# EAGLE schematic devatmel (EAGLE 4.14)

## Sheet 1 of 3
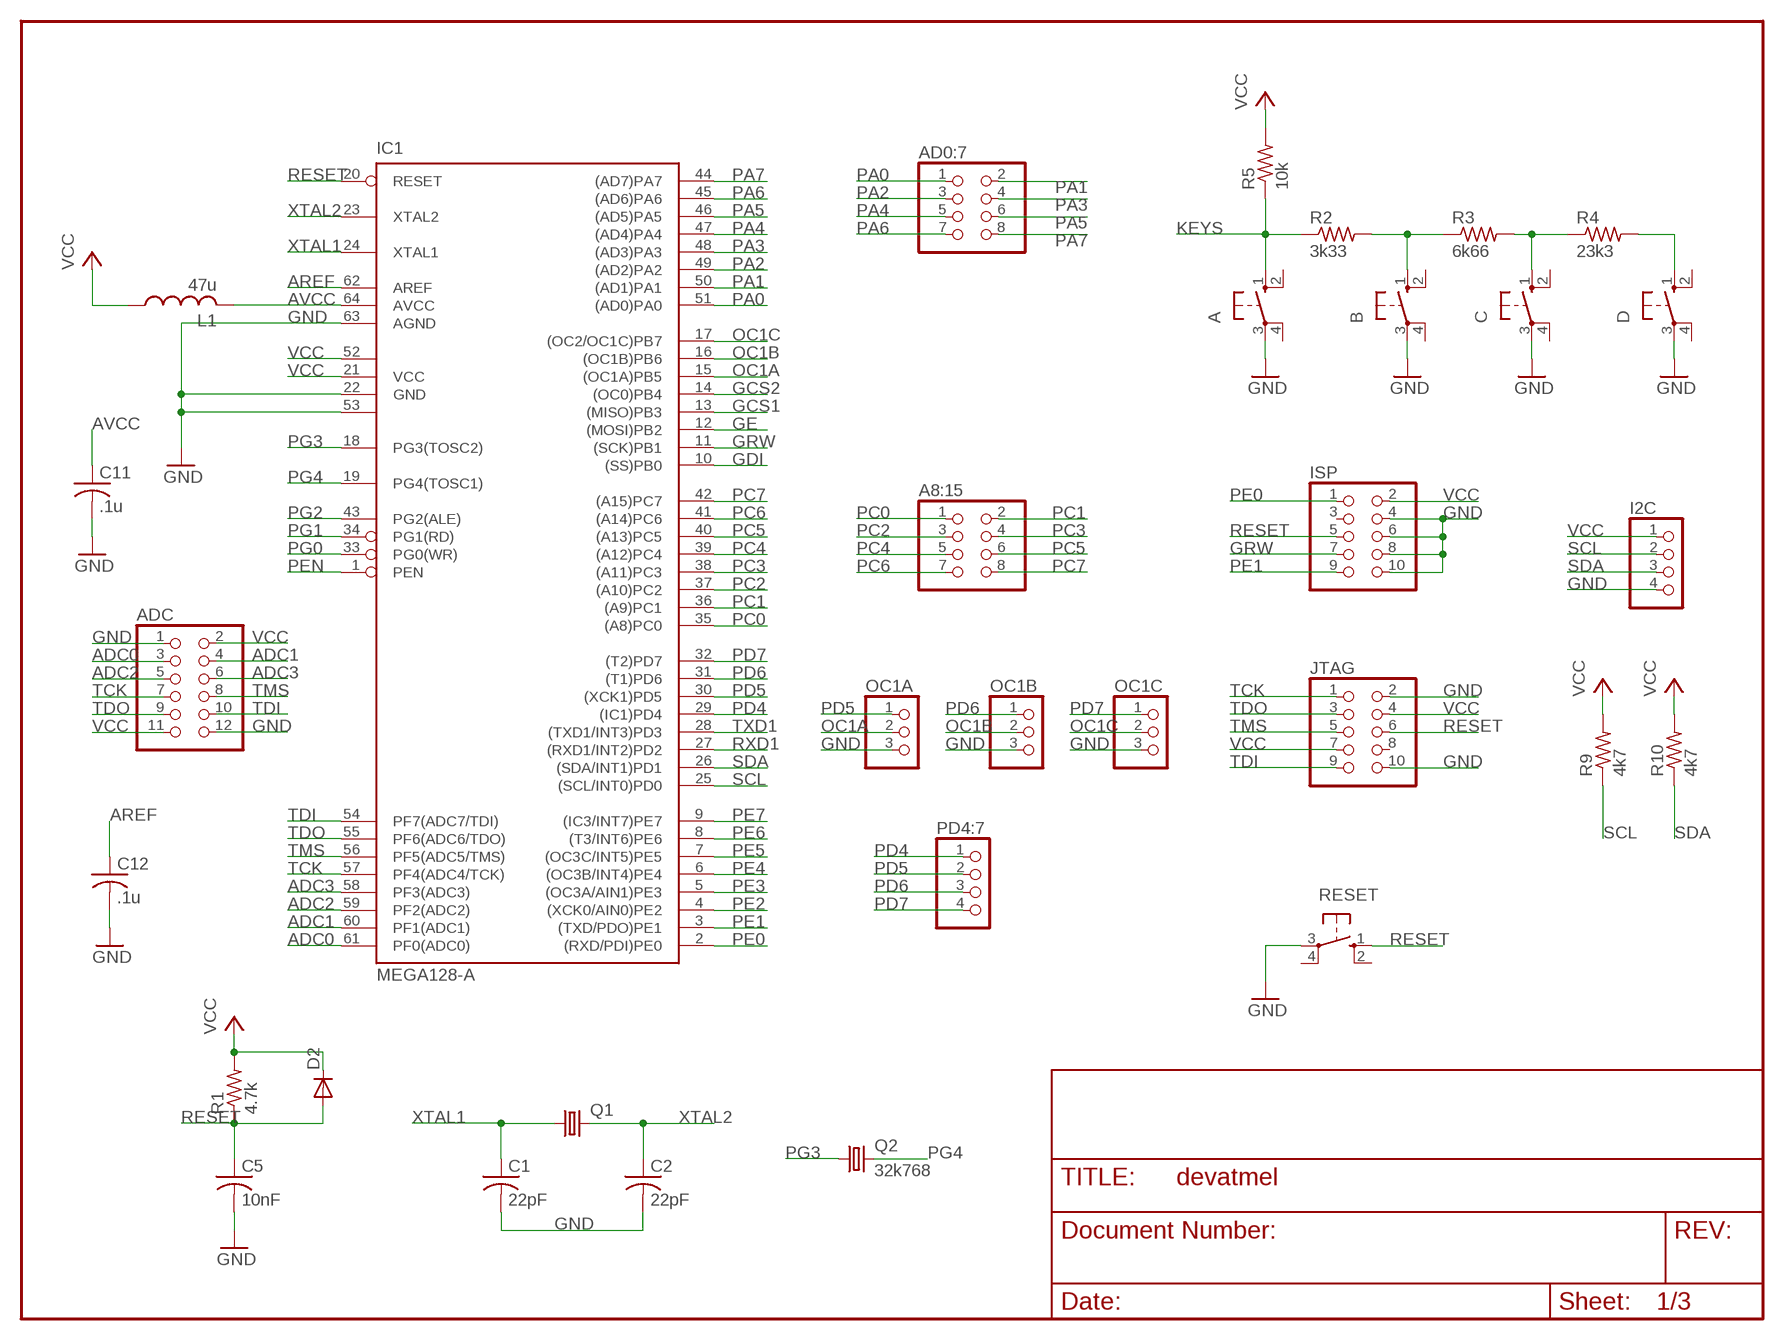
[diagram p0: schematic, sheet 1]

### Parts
A  10-XX  [B3F-10XX]
A8:15  PINHD-2X4  [2X04]
AD0:7  PINHD-2X4  [2X04]
ADC  PINHD-2X6  [2X06]
B  10-XX  [B3F-10XX]
C  10-XX  [B3F-10XX]
C1  22pF  C-USC0603  [C0603]
C2  22pF  C-USC0603  [C0603]
C5  10nF  C-USC1206  [C1206]
C11  .1u  C-USC1206  [C1206]
C12  .1u  C-USC1206  [C1206]
D  10-XX  [B3F-10XX]
D2  DIODE-SOD80C  [SOD80C]
I2C  PINHD-1X4  [1X04]
IC1  MEGA128-A  [TQFP64]
ISP  HDR10KEYED  [HDR10KEYED]
JTAG  HDR10KEYED  [HDR10KEYED]
L1  47u  L-MED  [PANASONIC_D]
OC1A  PINHD-1X3  [1X03]
OC1B  PINHD-1X3  [1X03]
OC1C  PINHD-1X3  [1X03]
PD4:7  PINHD-1X4  [1X04]
Q1  CRYTALSM49  [SM49]
Q2  32k768  CRYTALTC38H  [TC38H]
R1  4.7k  R-US_R0805  [R0805]
R2  3k33  R-US_R0805  [R0805]
R3  6k66  R-US_R0805  [R0805]
R4  23k3  R-US_R0805  [R0805]
R5  10k  R-US_R0805  [R0805]
R9  4k7  R-US_R0805  [R0805]
R10  4k7  R-US_R0805  [R0805]
RESET  10-XX  [B3F-10XX]

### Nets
ADC0 [signal]: ADC.3 IC1.61(PF0(ADC0))
ADC1 [signal]: ADC.4 IC1.60(PF1(ADC1))
ADC2 [signal]: ADC.5 IC1.59(PF2(ADC2))
ADC3 [signal]: ADC.6 IC1.58(PF3(ADC3))
AREF [signal]: C12.1 IC1.62(AREF)
AVCC [signal]: C11.1 IC1.64(AVCC) L1.2
GCS1 [signal]: IC1.13((MISO)PB3) ; also sheet 3
GCS2: IC1.14((OC0)PB4) ; also sheet 3
GDI: IC1.10((SS)PB0) ; also sheet 3
GE: IC1.12((MOSI)PB2) ; also sheet 3
GND [power]: A.3(P) ADC.1 ADC.12 B.3(P) C1.2 C2.2 C5.2 C11.2 C12.2 C.3(P) D.3(P) I2C.4 IC1.22(GND) IC1.53(GND1) IC1.63(AGND) ISP.4 ISP.6 ISP.8 ISP.10 JTAG.2 JTAG.10 OC1A.3 OC1B.3 OC1C.3 RESET.3(P) ; also sheet 2,3
GRW: IC1.11((SCK)PB1) ISP.7 ; also sheet 3
KEYS: A.1(S) R2.1 R5.1 ; also sheet 2
N$4: B.1(S) R2.2 R3.1
N$5: C.1(S) R3.2 R4.1
N$8: D.1(S) R4.2
OC1A [signal]: IC1.15((OC1A)PB5) OC1A.2 ; also sheet 3
OC1B [signal]: IC1.16((OC1B)PB6) OC1B.2 ; also sheet 3
OC1C: IC1.17((OC2/OC1C)PB7) OC1C.2 ; also sheet 3
PA0 [signal]: AD0:7.1 IC1.51((AD0)PA0) ; also sheet 2
PA1 [signal]: AD0:7.2 IC1.50((AD1)PA1) ; also sheet 2
PA2 [signal]: AD0:7.3 IC1.49((AD2)PA2) ; also sheet 2
PA3 [signal]: AD0:7.4 IC1.48((AD3)PA3) ; also sheet 2
PA4 [signal]: AD0:7.5 IC1.47((AD4)PA4) ; also sheet 2
PA5 [signal]: AD0:7.6 IC1.46((AD5)PA5) ; also sheet 2
PA6 [signal]: AD0:7.7 IC1.45((AD6)PA6) ; also sheet 2
PA7 [signal]: AD0:7.8 IC1.44((AD7)PA7) ; also sheet 2
PC0 [signal]: A8:15.1 IC1.35((A8)PC0) ; also sheet 2
PC1 [signal]: A8:15.2 IC1.36((A9)PC1) ; also sheet 2
PC2 [signal]: A8:15.3 IC1.37((A10)PC2) ; also sheet 2
PC3 [signal]: A8:15.4 IC1.38((A11)PC3) ; also sheet 2
PC4 [signal]: A8:15.5 IC1.39((A12)PC4) ; also sheet 2
PC5 [signal]: A8:15.6 IC1.40((A13)PC5) ; also sheet 2
PC6 [signal]: A8:15.7 IC1.41((A14)PC6) ; also sheet 2
PC7 [signal]: A8:15.8 IC1.42((A15)PC7) ; also sheet 2
PD4 [signal]: IC1.29((IC1)PD4) PD4:7.1 ; also sheet 2
PD5 [signal]: IC1.30((XCK1)PD5) OC1A.1 PD4:7.2
PD6 [signal]: IC1.31((T1)PD6) OC1B.1 PD4:7.3
PD7 [signal]: IC1.32((T2)PD7) OC1C.1 PD4:7.4
PE0 [signal]: IC1.2((RXD/PDI)PE0) ISP.1 ; also sheet 2,3
PE1: IC1.3((TXD/PDO)PE1) ISP.9 ; also sheet 2,3
PE2 [signal]: IC1.4((XCK0/AIN0)PE2) ; also sheet 2,3
PE3 [signal]: IC1.5((OC3A/AIN1)PE3) ; also sheet 3
PE4 [signal]: IC1.6((OC3B/INT4)PE4) ; also sheet 3
PE5 [signal]: IC1.7((OC3C/INT5)PE5) ; also sheet 3
PE6 [signal]: IC1.8((T3/INT6)PE6) ; also sheet 3
PE7 [signal]: IC1.9((IC3/INT7)PE7) ; also sheet 2,3
PEN [signal]: IC1.1(PEN)
PG0 [signal]: IC1.33(PG0(WR)) ; also sheet 2
PG1 [signal]: IC1.34(PG1(RD)) ; also sheet 2
PG2 [signal]: IC1.43(PG2(ALE)) ; also sheet 2
PG3 [signal]: IC1.18(PG3(TOSC2)) Q2.1
PG4 [signal]: IC1.19(PG4(TOSC1)) Q2.2
RESET [signal]: C5.1 D2.A IC1.20(RESET) ISP.5 JTAG.6 R1.1 RESET.1(S) ; also sheet 2,3
RXD1 [signal]: IC1.27((RXD1/INT2)PD2) ; also sheet 2
SCL [signal]: I2C.2 IC1.25((SCL/INT0)PD0) R9.1
SDA [signal]: I2C.3 IC1.26((SDA/INT1)PD1) R10.1
TCK [signal]: ADC.7 IC1.57(PF4(ADC4/TCK)) JTAG.1
TDI [signal]: ADC.10 IC1.54(PF7(ADC7/TDI)) JTAG.9 ; also sheet 2
TDO [signal]: ADC.9 IC1.55(PF6(ADC6/TDO)) JTAG.3
TMS [signal]: ADC.8 IC1.56(PF5(ADC5/TMS)) JTAG.5
TXD1 [signal]: IC1.28((TXD1/INT3)PD3) ; also sheet 2
VCC [power]: ADC.2 ADC.11 D2.C I2C.1 IC1.21(VCC) IC1.52(VCC1) ISP.2 JTAG.4 JTAG.7 L1.1 R1.2 R5.2 R9.2 R10.2 ; also sheet 2,3
XTAL1 [signal]: C1.1 IC1.24(XTAL1) Q1.1
XTAL2 [signal]: C2.1 IC1.23(XTAL2) Q1.2
Unconnected: A.2(S1) A.4(P1) B.2(S1) B.4(P1) C.2(S1) C.4(P1) D.2(S1) D.4(P1) ISP.3 JTAG.8 RESET.2(S1) RESET.4(P1)

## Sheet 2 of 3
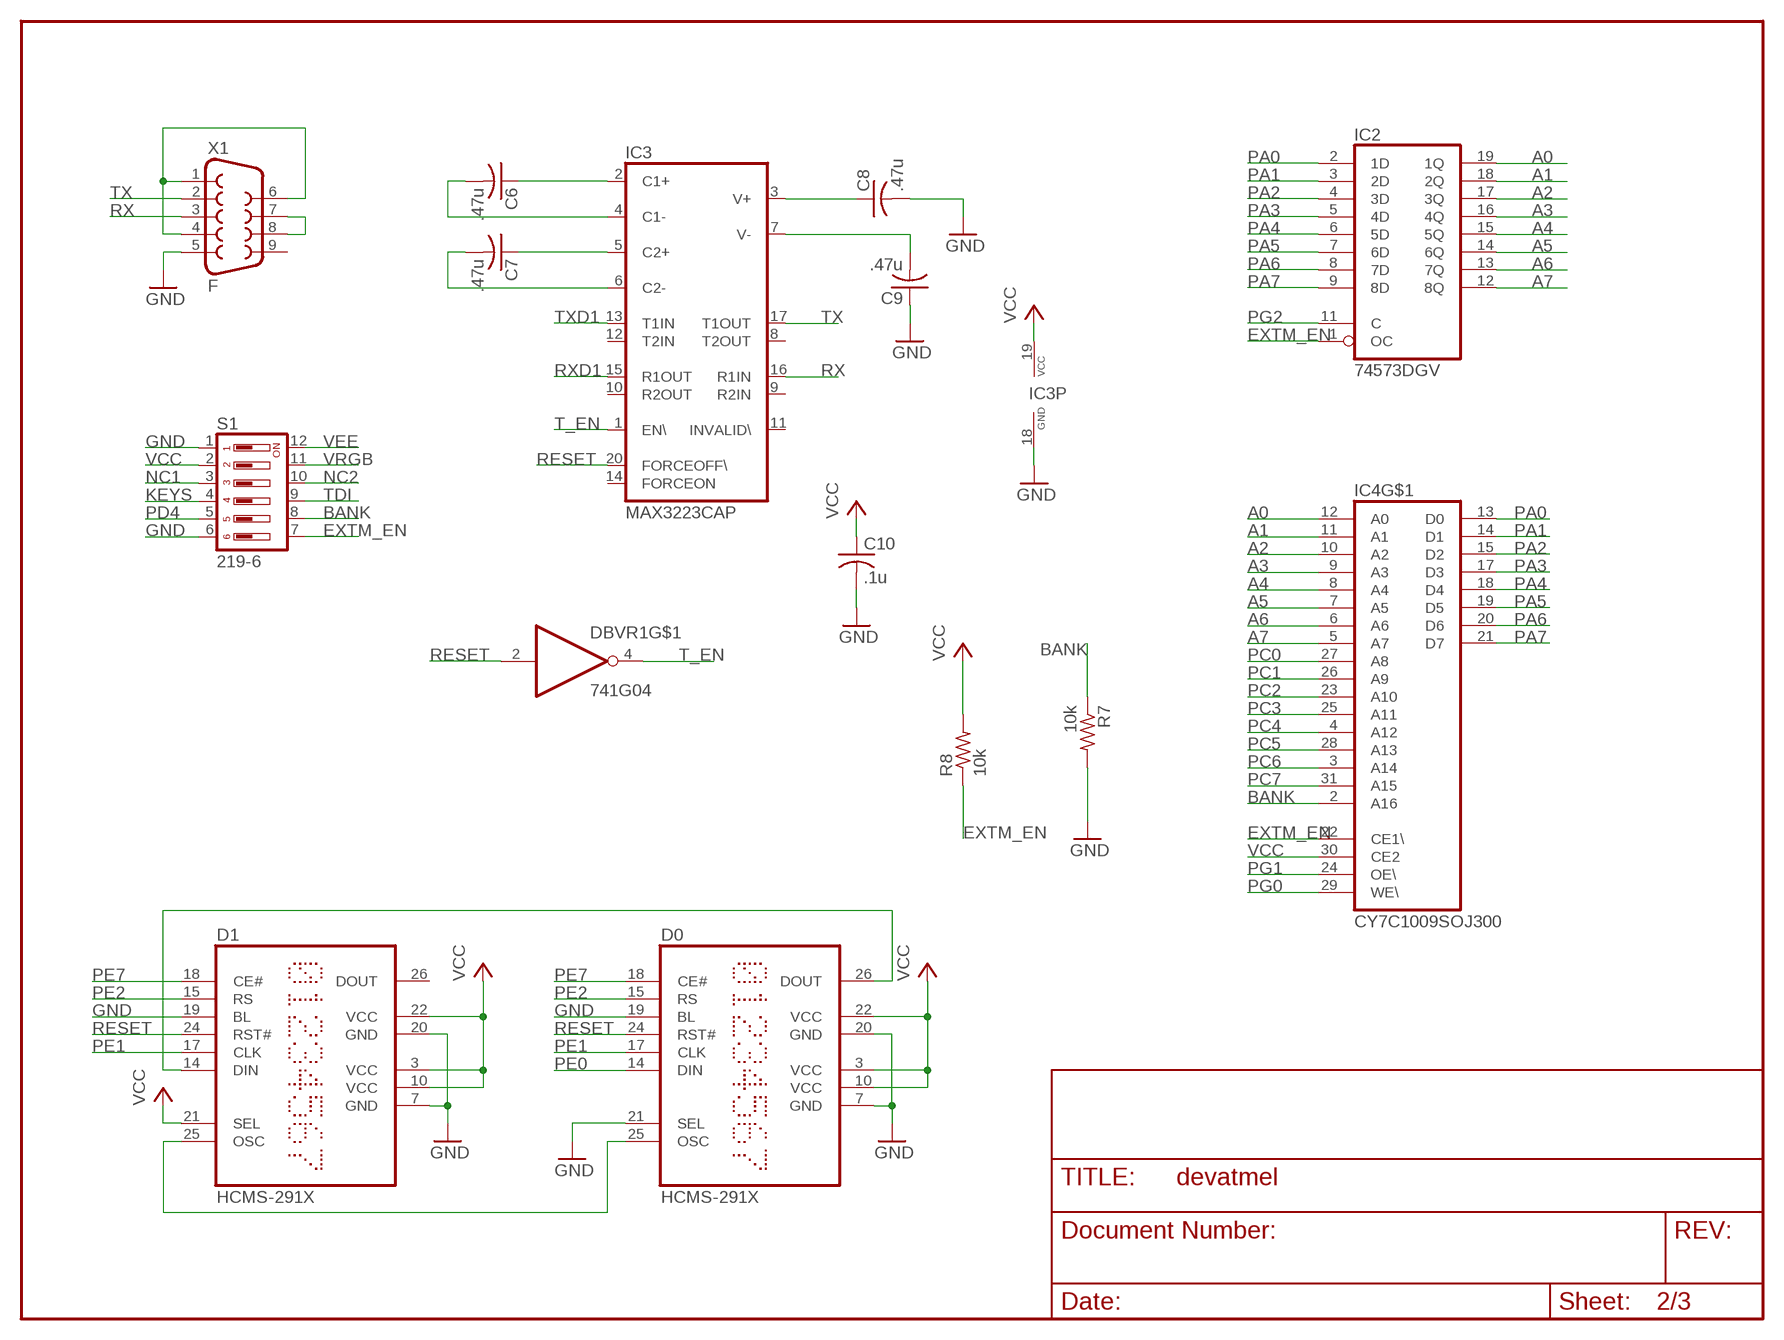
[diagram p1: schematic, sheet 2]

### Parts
C6  .47u  C-USC1206  [C1206]
C7  .47u  C-USC1206  [C1206]
C8  .47u  C-USC1206  [C1206]
C9  .47u  C-USC1206  [C1206]
C10  .1u  C-USC1206  [C1206]
D0  HCMS-291X  [HCMS-291X]
D1  HCMS-291X  [HCMS-291X]
DBVR1  741G04  [SOT23-5L]
IC2  74573DGV  [SSOP20]
IC3  MAX3223CAP  [SSOP20]
IC4  CY7C1009SOJ300  [SOJ32/3]
R7  10k  R-US_R0805  [R0805]
R8  10k  R-US_R0805  [R0805]
S1  219-6  [219-6]
X1  F  F09HP  [F09HP]

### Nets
A0: IC2.19(1Q) IC4.12(A0)
A1: IC2.18(2Q) IC4.11(A1)
A2: IC2.17(3Q) IC4.10(A2)
A3: IC2.16(4Q) IC4.9(A3)
A4: IC2.15(5Q) IC4.8(A4)
A5: IC2.14(6Q) IC4.7(A5)
A6: IC2.13(7Q) IC4.6(A6)
A7: IC2.12(8Q) IC4.5(A7)
BANK: IC4.2(A16) R7.1 S1.8
EXTM_EN: IC2.1(OC) IC4.22(CE1\) R8.1 S1.7
GND [power]: C8.2 C9.1 C10.2 D0.7(GND) D0.19(BL) D0.20(GND) D0.21(SEL) D1.7(GND) D1.19(BL) D1.20(GND) IC3.18(GND) R7.2 S1.1 S1.6 X1.5 ; also sheet 1,3
KEYS: S1.4 ; also sheet 1
N$1 [signal]: C6.1 IC3.2(C1+)
N$2 [signal]: C6.2 IC3.4(C1-)
N$6 [signal]: C7.1 IC3.5(C2+)
N$7 [signal]: C7.2 IC3.6(C2-)
N$15 [signal]: C8.1 IC3.3(V+)
N$16 [signal]: C9.2 IC3.7(V-)
N$26: D0.26(DOUT) D1.14(DIN)
N$28: D0.25(OSC) D1.25(OSC)
N$49: X1.7 X1.8
N$50: X1.1 X1.4 X1.6
NC1: S1.3
NC2: S1.10
PA0 [signal]: IC2.2(1D) IC4.13(D0) ; also sheet 1
PA1 [signal]: IC2.3(2D) IC4.14(D1) ; also sheet 1
PA2 [signal]: IC2.4(3D) IC4.15(D2) ; also sheet 1
PA3 [signal]: IC2.5(4D) IC4.17(D3) ; also sheet 1
PA4 [signal]: IC2.6(5D) IC4.18(D4) ; also sheet 1
PA5 [signal]: IC2.7(6D) IC4.19(D5) ; also sheet 1
PA6 [signal]: IC2.8(7D) IC4.20(D6) ; also sheet 1
PA7 [signal]: IC2.9(8D) IC4.21(D7) ; also sheet 1
PC0 [signal]: IC4.27(A8) ; also sheet 1
PC1 [signal]: IC4.26(A9) ; also sheet 1
PC2 [signal]: IC4.23(A10) ; also sheet 1
PC3 [signal]: IC4.25(A11) ; also sheet 1
PC4 [signal]: IC4.4(A12) ; also sheet 1
PC5 [signal]: IC4.28(A13) ; also sheet 1
PC6 [signal]: IC4.3(A14) ; also sheet 1
PC7 [signal]: IC4.31(A15) ; also sheet 1
PD4 [signal]: S1.5 ; also sheet 1
PE0 [signal]: D0.14(DIN) ; also sheet 1,3
PE1: D0.17(CLK) D1.17(CLK) ; also sheet 1,3
PE2 [signal]: D0.15(RS) D1.15(RS) ; also sheet 1,3
PE7 [signal]: D0.18(CE#) D1.18(CE#) ; also sheet 1,3
PG0 [signal]: IC4.29(WE\) ; also sheet 1
PG1 [signal]: IC4.24(OE\) ; also sheet 1
PG2 [signal]: IC2.11(C) ; also sheet 1
RESET [signal]: D0.24(RST#) D1.24(RST#) DBVR1.2(I) IC3.20(FORCEOFF\) ; also sheet 1,3
RX: IC3.16(R1IN) X1.3
RXD1 [signal]: IC3.15(R1OUT) ; also sheet 1
T_EN: DBVR1.4(O) IC3.1(EN\)
TDI [signal]: S1.9 ; also sheet 1
TX: IC3.17(T1OUT) X1.2
TXD1 [signal]: IC3.13(T1IN) ; also sheet 1
VCC [power]: C10.1 D0.3(VCC) D0.10(VCC) D0.22(VCC) D1.3(VCC) D1.10(VCC) D1.21(SEL) D1.22(VCC) IC3.19(VCC) IC4.30(CE2) R8.2 S1.2 ; also sheet 1,3
VEE: S1.12 ; also sheet 3
VRGB: S1.11 ; also sheet 3
Unconnected: D1.26(DOUT) IC3.8(T2OUT) IC3.9(R2IN) IC3.10(R2OUT) IC3.11(INVALID\) IC3.12(T2IN) IC3.14(FORCEON) X1.9

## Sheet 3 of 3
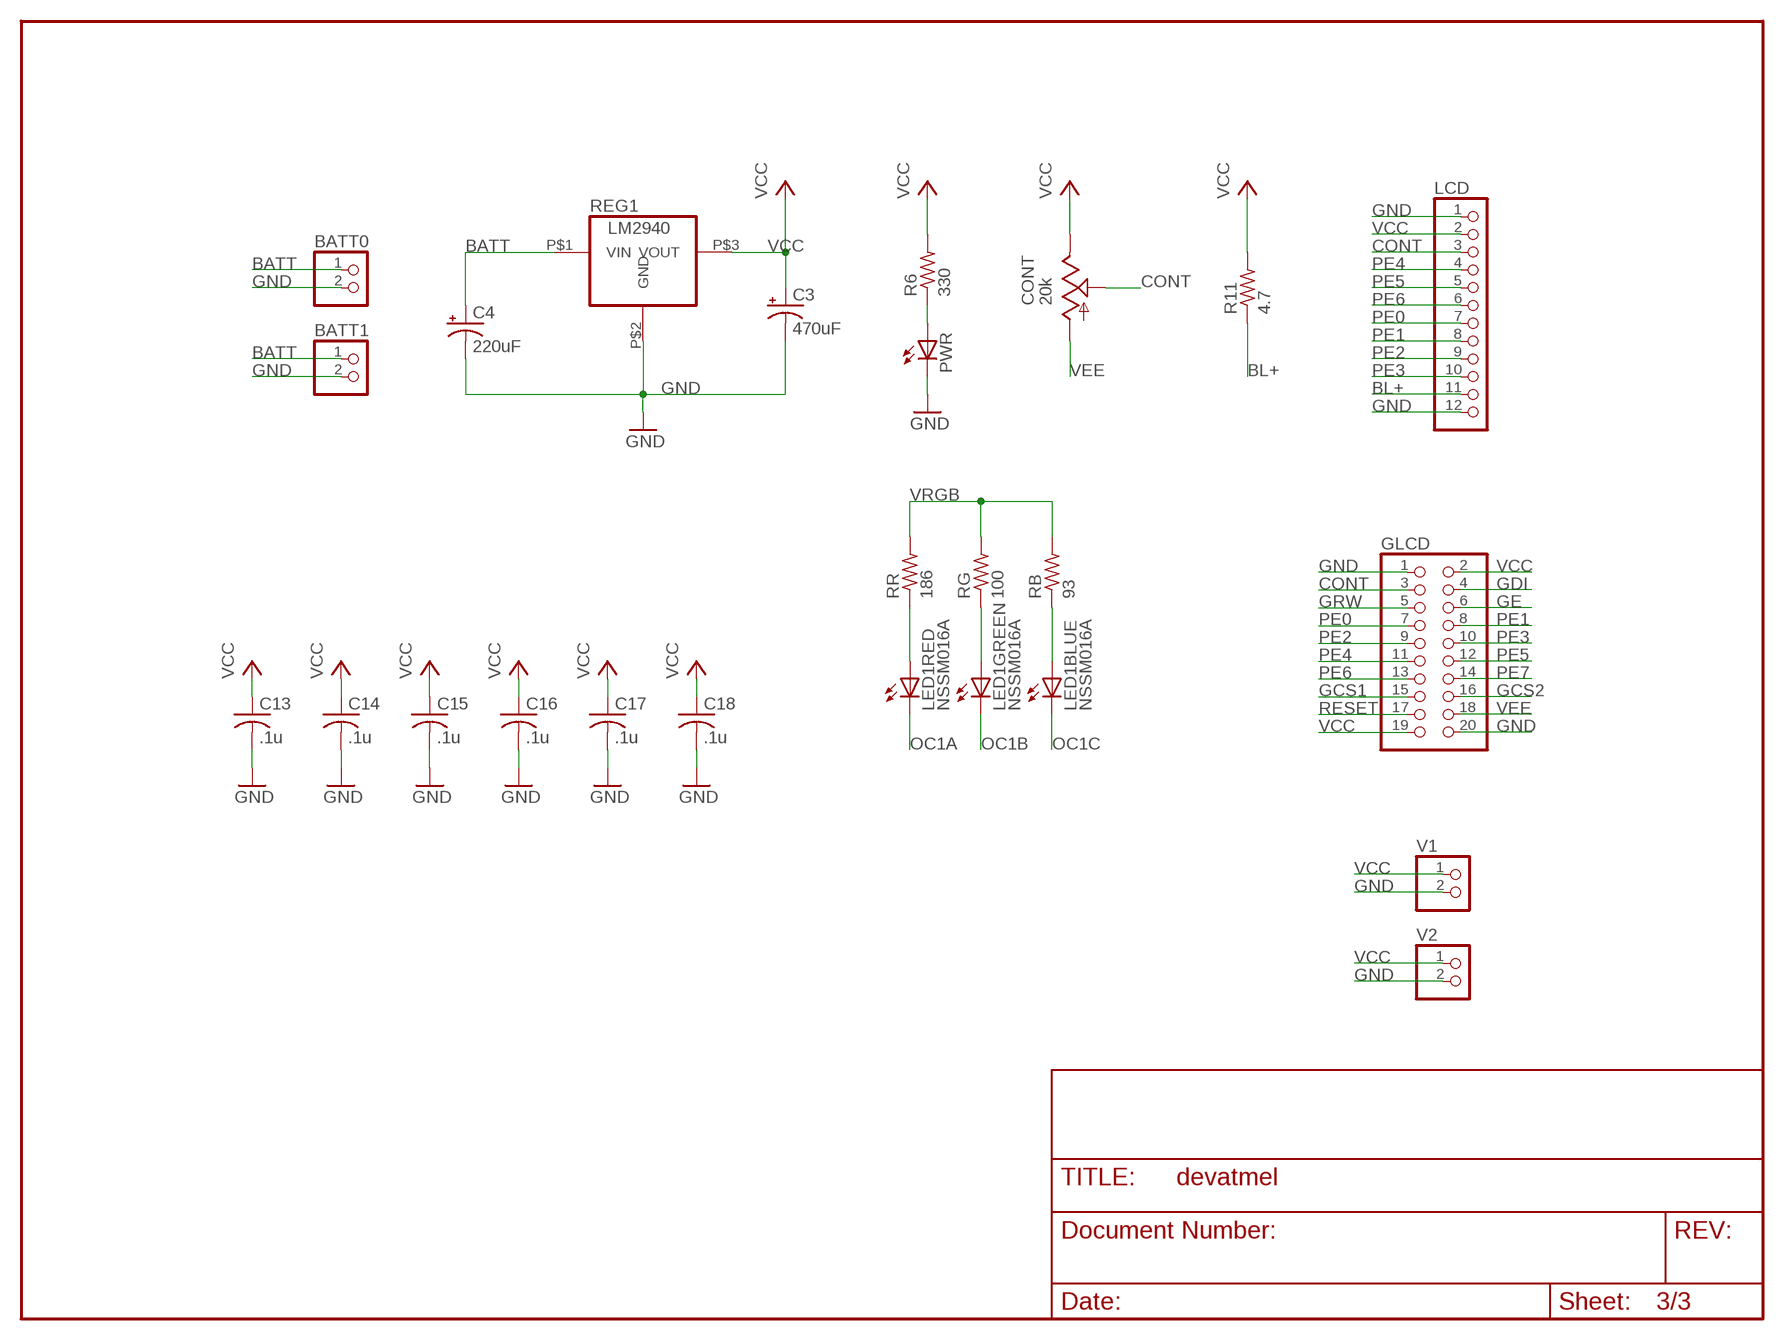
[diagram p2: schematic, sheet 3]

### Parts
BATT0  PINHD-1X2  [1X02]
BATT1  PINHD-1X2  [1X02]
C3  470uF  CPOL-USF  [PANASONIC_F]
C4  220uF  CPOL-USF  [PANASONIC_F]
C13  .1u  C-USC1206  [C1206]
C14  .1u  C-USC1206  [C1206]
C15  .1u  C-USC1206  [C1206]
C16  .1u  C-USC1206  [C1206]
C17  .1u  C-USC1206  [C1206]
C18  .1u  C-USC1206  [C1206]
CONT  20k  TRIM_US-B25P  [B25P]
GLCD  PINHD-2X10  [2X10]
LCD  PINHD-1X12  [1X12]
LED1  NSSM016A  [NSSM016A]
PWR  LEDCHIPLED_0805  [CHIPLED_0805]
R6  330  R-US_R0805  [R0805]
R11  4.7  R-US_R0805  [R0805]
RB  93  R-US_R0805  [R0805]
REG1  LM2940  [DD-3DL]
RG  100  R-US_R0805  [R0805]
RR  186  R-US_R0805  [R0805]
V1  PINHD-1X2  [1X02]
V2  PINHD-1X2  [1X02]

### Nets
BATT [power]: BATT0.1 BATT1.1 C4.+ REG1.P$1(VIN)
BL+ [signal]: LCD.11 R11.1
CONT [signal]: CONT.S GLCD.3 LCD.3
GCS1 [signal]: GLCD.15 ; also sheet 1
GCS2: GLCD.16 ; also sheet 1
GDI: GLCD.4 ; also sheet 1
GE: GLCD.6 ; also sheet 1
GND [power]: BATT0.2 BATT1.2 C3.- C4.- C13.2 C14.2 C15.2 C16.2 C17.2 C18.2 GLCD.1 GLCD.20 LCD.1 LCD.12 PWR.C REG1.P$2(GND) V1.2 V2.2 ; also sheet 1,2
GRW: GLCD.5 ; also sheet 1
N$3: PWR.A R6.1
N$22: LED1.4(RED:A) RR.1
N$23: LED1.5(GREEN:A) RG.1
N$24: LED1.6(BLUE:A) RB.1
OC1A [signal]: LED1.3(RED:C) ; also sheet 1
OC1B [signal]: LED1.2(GREEN:C) ; also sheet 1
OC1C: LED1.1(BLUE:C) ; also sheet 1
PE0 [signal]: GLCD.7 LCD.7 ; also sheet 1,2
PE1: GLCD.8 LCD.8 ; also sheet 1,2
PE2 [signal]: GLCD.9 LCD.9 ; also sheet 1,2
PE3 [signal]: GLCD.10 LCD.10 ; also sheet 1
PE4 [signal]: GLCD.11 LCD.4 ; also sheet 1
PE5 [signal]: GLCD.12 LCD.5 ; also sheet 1
PE6 [signal]: GLCD.13 LCD.6 ; also sheet 1
PE7 [signal]: GLCD.14 ; also sheet 1,2
RESET [signal]: GLCD.17 ; also sheet 1,2
VCC [power]: C3.+ C13.1 C14.1 C15.1 C16.1 C17.1 C18.1 CONT.E GLCD.2 GLCD.19 LCD.2 R6.2 R11.2 REG1.P$3(VOUT) V1.1 V2.1 ; also sheet 1,2
VEE: CONT.A GLCD.18 ; also sheet 2
VRGB: RB.2 RG.2 RR.2 ; also sheet 2

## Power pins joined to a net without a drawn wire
GND: DBVR1.3(GND) IC2.10(GND) IC4.16(P:GND)
VCC: DBVR1.5(VCC) IC2.20(VCC) IC4.32(P:VCC)

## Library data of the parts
A B C D RESET = switch-omron:10-XX: OMRON SWITCH
A8:15 AD0:7 = pinhead:PINHD-2X4: PIN HEADER
ADC = pinhead:PINHD-2X6: PIN HEADER
BATT0 BATT1 V1 V2 = pinhead:PINHD-1X2: PIN HEADER
C1 C2 C5-C18 = rcl:C-US: CAPACITOR, American symbol
C3 C4 = rcl:CPOL-US: POLARIZED CAPACITOR, American symbol
CONT = pot:TRIM_US-: POTENTIOMETER
D0 D1 = display:HCMS-291X
D2 = diode:DIODE-: DIODE
DBVR1 = 74xx:74*1G04
GLCD = pinhead:PINHD-2X10: PIN HEADER
I2C PD4:7 = pinhead:PINHD-1X4: PIN HEADER
IC1 = avr:MEGA128: MICROCONTROLLER 128 Kbytes FLASH 4 Kbytes SRAM 4 Kbytes EEPROM DUAL USART 8-channel 10 bit ADC
IC2 = 74xx:74*573: 8-bit D latch BUS DRIVER
IC3 = maxim:MAX3223*: RS-232 Transceivers with AutoShutdown 1µA Supply-Current, True +3V to +5.5V http://dbserv.maxim-ic.com/
IC4 = memory:CY7C1009
ISP JTAG = hdr-extra:HDR10KEYED
L1 = inductor:L-MED
LCD = pinhead:PINHD-1X12: PIN HEADER
LED1 = nichia:NSSM016A
OC1A OC1B OC1C = pinhead:PINHD-1X3: PIN HEADER
PWR = led:LED: LED
Q1 Q2 = crystal:CRYTAL: CRYSTAL
R1-R11 RB RG RR = rcl:R-US_: RESISTOR, American symbol
REG1 = LM2940:LM2940
S1 = cts-switch:219-6
X1 = con-subd:F09: SUB-D

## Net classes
1 signal: width 0.254 mm
2 power: width 0.381 mm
